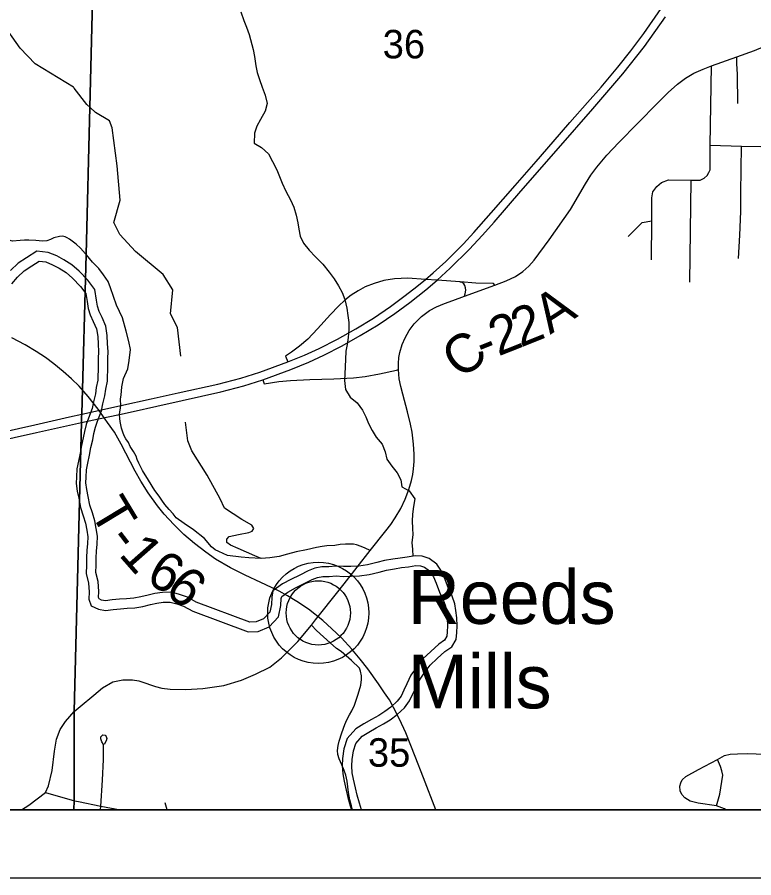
# Model space of a CAD drawing. Extents: x 0 to 34, y 0 to 22.
# Drawn here: x 4.467 to 5.55, y 14 to 15.265 of the extents above; entities that cross this region are included whole.
import ezdxf

# ---------------------------------------------------------------- set-up
doc = ezdxf.new("R2010")
doc.units = 0
for name, color, linetype in [('GM_X_Corporation', 7, 'Continuous'), ('GM_X_County_Road', 7, 'Continuous'), ('GM_X_County_Road_Text', 7, 'Continuous'), ('GM_X_Interchange_Ramps', 7, 'Continuous'), ('GM_X_Minor_River', 7, 'Continuous'), ('GM_X_Rail_Line', 7, 'Continuous'), ('GM_X_Section_Text', 7, 'Continuous'), ('GM_X_Township_Road', 7, 'Continuous'), ('GM_X_Township_Road_Text', 7, 'Continuous'), ('GM_X_Unincorporated', 7, 'Continuous'), ('GM_X_Unincorporated_Location', 7, 'Continuous'), ('GM_X_Unincorporated_Text', 7, 'Continuous'), ('GM_X_US_Route', 7, 'Continuous'), ('SH_Data', 7, 'Continuous')]:
    doc.layers.add(name, color=color, linetype=linetype)

msp = doc.modelspace()

# ---------------------------------------------------------------- linework, layer by layer
at = {"layer": 'GM_X_Corporation'}
msp.add_lwpolyline([(5.6014, 15.7658), (5.4664, 15.7674), (4.5888, 15.778), (4.5873, 15.6794), (4.5738, 15.1325), (4.5685, 14.9157), (4.5617, 14.6817), (4.5616, 14.6767), (4.5614, 14.6695), (4.5505, 14.2449), (4.5507, 14.1138), (4.5503, 14.1), (8.9, 14.1)], dxfattribs=at)
msp.add_lwpolyline([(2.1, 15.7148), (2.1, 14.1), (4.5503, 14.1), (4.5507, 14.1138), (4.5505, 14.2449), (4.5614, 14.6695), (4.5616, 14.6767), (4.5617, 14.6817), (4.5685, 14.9157), (4.5738, 15.1325), (4.5873, 15.6794), (4.2138, 15.6834), (3.9277, 15.6898), (3.3171, 15.6975), (2.4078, 15.7088)], close=True, dxfattribs=at)
at = {"layer": 'GM_X_County_Road'}
msp.add_line((4.8997, 14.3711), (4.9056, 14.3789), dxfattribs=at)
for points in [[(5.4875, 15.1929), (5.5249, 15.2062), (5.5509, 15.2158), (5.5765, 15.2264)], [(5.169, 14.8707), (5.1858, 14.877), (5.1997, 14.8836), (5.2102, 14.8908), (5.2192, 14.8985), (5.227, 14.9074), (5.2489, 14.9374), (5.2804, 14.9818), (5.3025, 15.0199), (5.3105, 15.0326), (5.319, 15.0444), (5.334, 15.0616), (5.3517, 15.0802), (5.3796, 15.1089), (5.4083, 15.1384), (5.4241, 15.1541), (5.4375, 15.1661), (5.4496, 15.1749), (5.4617, 15.1821), (5.4756, 15.1882), (5.4875, 15.1929)], [(5.0276, 14.7468), (5.0274, 14.7555), (5.0282, 14.7645), (5.0295, 14.7719), (5.0327, 14.7834), (5.0371, 14.7935), (5.0432, 14.8043), (5.0507, 14.8141), (5.0614, 14.8248), (5.0733, 14.8336), (5.0834, 14.8389), (5.0954, 14.844), (5.1074, 14.8483), (5.1245, 14.8546), (5.169, 14.8707)], [(4.9861, 14.4808), (5.0089, 14.5096), (5.0161, 14.5193), (5.0227, 14.5289), (5.0311, 14.5427), (5.0375, 14.5563), (5.0428, 14.5706), (5.0467, 14.5839), (5.0486, 14.5925), (5.0498, 14.601), (5.0505, 14.6115), (5.0505, 14.6225), (5.0497, 14.6373), (5.0475, 14.655), (5.0453, 14.6665), (5.0406, 14.6849), (5.0338, 14.7107), (5.0309, 14.7219), (5.0287, 14.733), (5.0276, 14.7468)], [(4.9056, 14.3789), (4.9151, 14.3914), (4.9474, 14.432), (4.9861, 14.4808)], [(4.6488, 14.2883), (4.6703, 14.2813), (4.6796, 14.2784), (4.6916, 14.2772), (4.7148, 14.2769), (4.74, 14.2781), (4.7706, 14.2825), (4.7966, 14.2904), (4.8175, 14.2992), (4.8381, 14.3093), (4.8557, 14.3232), (4.8795, 14.347), (4.8997, 14.3711)], [(4.473, 14.1), (4.484, 14.1067), (4.5085, 14.1253), (4.5127, 14.1352), (4.5181, 14.1578), (4.5216, 14.1861), (4.5247, 14.2038), (4.5303, 14.2179), (4.5377, 14.2295), (4.5507, 14.2443), (4.5595, 14.2518), (4.5796, 14.2683), (4.5925, 14.2793), (4.6074, 14.2878), (4.622, 14.2909), (4.6365, 14.2911), (4.6458, 14.2892), (4.6488, 14.2883)]]:
    msp.add_lwpolyline(points, dxfattribs=at)
at = {"layer": 'GM_X_Interchange_Ramps'}
for points in [[(5.169, 14.8707), (5.1671, 14.873), (5.1412, 14.8737), (5.1181, 14.8759), (5.0845, 14.8781), (5.0671, 14.8793), (5.0412, 14.881), (5.0214, 14.8801), (5.0059, 14.8775), (4.9916, 14.8734), (4.9785, 14.8681), (4.9681, 14.8627), (4.9579, 14.856), (4.9485, 14.8487), (4.9392, 14.8401), (4.9275, 14.8278), (4.9082, 14.8067), (4.894, 14.7915), (4.8822, 14.7812), (4.8701, 14.7722), (4.8615, 14.7666), (4.8649, 14.7579)], [(5.1245, 14.8546), (5.1255, 14.8579), (5.1265, 14.8633), (5.1262, 14.867), (5.125, 14.8705), (5.1234, 14.8728), (5.1213, 14.8745), (5.118, 14.8751), (5.1181, 14.8759)], [(4.8279, 14.7316), (4.83, 14.7259), (4.8514, 14.7291), (4.8686, 14.7309), (4.8972, 14.7323), (4.9324, 14.7331), (4.9616, 14.7344), (4.9787, 14.7365), (4.9996, 14.7405), (5.0245, 14.7457), (5.0276, 14.7468)]]:
    msp.add_lwpolyline(points, dxfattribs=at)
at = {"layer": 'GM_X_Minor_River'}
for points in [[(4.7958, 15.2723), (4.8002, 15.2598), (4.8042, 15.25), (4.8082, 15.2391), (4.814, 15.2172), (4.8158, 15.2066), (4.8179, 15.1929), (4.8197, 15.1831), (4.8233, 15.1732), (4.8273, 15.1619), (4.8313, 15.1502), (4.8346, 15.1377), (4.8314, 15.1263), (4.8245, 15.1143), (4.8194, 15.1044), (4.8158, 15.094), (4.8153, 15.0796), (4.8261, 15.0729), (4.8365, 15.0636), (4.8421, 15.0523), (4.8488, 15.0403), (4.8524, 15.0305), (4.8564, 15.0207), (4.862, 15.009), (4.8687, 14.9962), (4.8735, 14.9853), (4.8771, 14.9736), (4.8796, 14.9626), (4.881, 14.9531), (4.8831, 14.9429), (4.8878, 14.9327), (4.8964, 14.9223), (4.9054, 14.9122), (4.9162, 14.9017), (4.9256, 14.8898), (4.933, 14.88), (4.9393, 14.8699), (4.9448, 14.8601), (4.9484, 14.8495), (4.9517, 14.8371), (4.9531, 14.8261), (4.9544, 14.8158), (4.9546, 14.8056), (4.9537, 14.7941), (4.9521, 14.7835), (4.95, 14.7739), (4.9495, 14.7617), (4.9489, 14.7511), (4.9488, 14.74), (4.9482, 14.7305), (4.9496, 14.7173), (4.9563, 14.706), (4.9667, 14.6978), (4.9745, 14.6873), (4.9793, 14.6775), (4.9833, 14.6677), (4.9888, 14.6572), (4.9947, 14.6474), (5.0033, 14.6373), (5.0077, 14.626), (5.0106, 14.6151), (5.0176, 14.6049), (5.0258, 14.5952), (5.031, 14.5847), (5.0323, 14.5744), (5.0431, 14.5686), (5.0513, 14.5566), (5.0496, 14.5455), (5.0483, 14.5345), (5.0474, 14.5238), (5.048, 14.5139), (5.0486, 14.5037), (5.0469, 14.4926), (5.0479, 14.4824), (5.0488, 14.4724)], [(4.7302, 14.405), (4.7172, 14.4123), (4.7056, 14.4162), (4.6938, 14.4195), (4.6804, 14.4193), (4.6695, 14.4175), (4.6595, 14.4154), (4.6488, 14.4127), (4.6382, 14.4109), (4.6274, 14.4101), (4.6175, 14.4093), (4.6065, 14.4084), (4.5969, 14.4071), (4.5908, 14.4081), (4.5872, 14.4099), (4.5865, 14.4119), (4.5867, 14.4205), (4.5857, 14.4352), (4.5827, 14.4486), (4.583, 14.4592), (4.5829, 14.4703), (4.5835, 14.4798), (4.5846, 14.4903), (4.5849, 14.5021), (4.5831, 14.5131), (4.5809, 14.5246), (4.5775, 14.5361), (4.5738, 14.5476), (4.5712, 14.5604), (4.5693, 14.5706), (4.5679, 14.5801), (4.5682, 14.5886), (4.5687, 14.5992), (4.5707, 14.6091), (4.5733, 14.621), (4.5754, 14.6323), (4.578, 14.6433), (4.5798, 14.6527), (4.5821, 14.662), (4.5852, 14.6708), (4.5908, 14.6859), (4.5927, 14.6965), (4.5957, 14.7082), (4.5972, 14.718), (4.5996, 14.7295), (4.6002, 14.7523), (4.6001, 14.763), (4.6004, 14.7735), (4.5999, 14.7846), (4.5994, 14.797), (4.597, 14.8105), (4.5916, 14.8232), (4.5873, 14.8323), (4.5851, 14.8398), (4.5836, 14.8489), (4.5811, 14.8645), (4.5708, 14.8781), (4.5582, 14.8913), (4.5473, 14.9007), (4.5357, 14.9079), (4.5252, 14.9137), (4.5126, 14.9189), (4.4958, 14.9207), (4.4806, 14.9111), (4.4681, 14.903), (4.4568, 14.8924)], [(4.4588, 14.8727), (4.4671, 14.8826), (4.4769, 14.8918), (4.4882, 14.8991), (4.4992, 14.906), (4.5091, 14.905), (4.519, 14.9009), (4.5285, 14.8956), (4.5389, 14.8893), (4.5484, 14.881), (4.5599, 14.8689), (4.5676, 14.8587), (4.5696, 14.8466), (4.5712, 14.8367), (4.574, 14.8272), (4.5786, 14.8174), (4.5833, 14.8064), (4.5853, 14.7954), (4.5857, 14.784), (4.5862, 14.7734), (4.5859, 14.7631), (4.586, 14.7525), (4.5854, 14.7312), (4.5832, 14.7205), (4.5818, 14.711), (4.5789, 14.6996), (4.577, 14.6897), (4.5718, 14.6756), (4.5685, 14.6661), (4.5659, 14.6558), (4.5641, 14.6463), (4.5615, 14.6352), (4.5594, 14.6238), (4.5568, 14.612), (4.5546, 14.601), (4.554, 14.5892), (4.5537, 14.5793), (4.5553, 14.5683), (4.5573, 14.5577), (4.56, 14.544), (4.5639, 14.5319), (4.5671, 14.5213), (4.5691, 14.5106), (4.5707, 14.5012), (4.5704, 14.4913), (4.5693, 14.481), (4.5686, 14.4707), (4.5687, 14.4593), (4.5685, 14.4472), (4.5716, 14.4331), (4.5725, 14.4202), (4.5722, 14.4096), (4.5757, 14.3997), (4.5864, 14.3945), (4.5967, 14.3927), (4.6081, 14.3943), (4.6187, 14.3951), (4.6286, 14.396), (4.6399, 14.3968), (4.6517, 14.3988), (4.6627, 14.4016), (4.6722, 14.4036), (4.6817, 14.4052), (4.6919, 14.4052), (4.7014, 14.4027), (4.7113, 14.3993), (4.725, 14.3918)], [(4.9731, 14.1), (4.97, 14.1098), (4.9667, 14.1215), (4.9642, 14.1321), (4.9613, 14.1449), (4.9596, 14.1544), (4.959, 14.1643), (4.9596, 14.1738), (4.9612, 14.1864), (4.9648, 14.1975), (4.9741, 14.2079), (4.9838, 14.2142), (4.9947, 14.2201), (5.0056, 14.2264), (5.0154, 14.2323), (5.0255, 14.2397), (5.0363, 14.2498), (5.0437, 14.2599), (5.048, 14.2695), (5.0528, 14.2791), (5.0583, 14.2906), (5.0653, 14.3006), (5.0741, 14.3122), (5.0846, 14.3223), (5.0958, 14.3324), (5.1059, 14.3394), (5.1121, 14.3502), (5.1134, 14.3605), (5.1136, 14.3704), (5.1134, 14.3818), (5.112, 14.3928), (5.1103, 14.4026), (5.1063, 14.4139), (5.1011, 14.4252), (5.0963, 14.4381), (5.0915, 14.449), (5.0837, 14.4606), (5.0728, 14.4692), (5.0625, 14.4728), (5.0522, 14.4729), (5.0401, 14.4712), (5.0299, 14.4698), (5.0193, 14.4681), (5.0068, 14.466), (4.9955, 14.4631), (4.9818, 14.4598), (4.969, 14.458), (4.9576, 14.4574), (4.9466, 14.4572), (4.9355, 14.4577), (4.9249, 14.4567), (4.915, 14.4569), (4.9044, 14.4548), (4.8946, 14.4512), (4.8826, 14.4449), (4.8694, 14.4385), (4.857, 14.4318), (4.8428, 14.4216), (4.8411, 14.4121), (4.8406, 14.4018), (4.8381, 14.3904), (4.8292, 14.3807), (4.8183, 14.3759), (4.8088, 14.3757), (4.7302, 14.405)], [(4.725, 14.3918), (4.8064, 14.3615), (4.8214, 14.3618), (4.8376, 14.3689), (4.8512, 14.3836), (4.8547, 14.4), (4.8552, 14.4105), (4.8558, 14.4134), (4.8646, 14.4197), (4.8759, 14.4259), (4.889, 14.4322), (4.9004, 14.4382), (4.9083, 14.4411), (4.9163, 14.4427), (4.9254, 14.4425), (4.9358, 14.4435), (4.9464, 14.4429), (4.9581, 14.4432), (4.9703, 14.4438), (4.9845, 14.4458), (4.9989, 14.4493), (5.0098, 14.4521), (5.0216, 14.4541), (5.032, 14.4558), (5.0421, 14.4571), (5.0532, 14.4587), (5.06, 14.4586), (5.0659, 14.4565), (5.0731, 14.4509), (5.079, 14.4421), (5.0831, 14.4327), (5.088, 14.4198), (5.0931, 14.4086), (5.0965, 14.399), (5.098, 14.3907), (5.0992, 14.3808), (5.0994, 14.3704), (5.0992, 14.3615), (5.0984, 14.3548), (5.0952, 14.3493), (5.0869, 14.3435), (5.0749, 14.3326), (5.0635, 14.3217), (5.0538, 14.309), (5.0459, 14.2977), (5.04, 14.2852), (5.0352, 14.2755), (5.0314, 14.2671), (5.0256, 14.2593), (5.0164, 14.2507), (5.0075, 14.2441), (4.9984, 14.2386), (4.9878, 14.2325), (4.9766, 14.2264), (4.9648, 14.2188), (4.9522, 14.2047), (4.9473, 14.1895), (4.9454, 14.1751), (4.9448, 14.1643), (4.9455, 14.1527), (4.9474, 14.1421), (4.9504, 14.1289), (4.953, 14.1179), (4.9564, 14.1057), (4.9582, 14.1)]]:
    msp.add_lwpolyline(points, dxfattribs=at)
at = {"layer": 'GM_X_Rail_Line'}
msp.add_lwpolyline([(5.0824, 14.1), (5.0641, 14.1469), (5.0522, 14.1781), (5.0382, 14.213), (5.0291, 14.2329), (5.0201, 14.2504), (5.0141, 14.2614), (5.0071, 14.2719), (4.9983, 14.2852), (4.9826, 14.3071), (4.9713, 14.3212), (4.9591, 14.336), (4.9437, 14.3524), (4.9295, 14.3659), (4.9161, 14.3779), (4.895, 14.3946), (4.8782, 14.4061), (4.8645, 14.4142), (4.8522, 14.4212), (4.8408, 14.4266), (4.8252, 14.434), (4.802, 14.4449), (4.7804, 14.4553), (4.7587, 14.4682), (4.7442, 14.4783), (4.7275, 14.4912), (4.7117, 14.5046), (4.697, 14.5191), (4.6831, 14.5343), (4.6731, 14.5466), (4.6594, 14.5658), (4.6486, 14.5828), (4.6403, 14.5973), (4.6198, 14.6372), (4.6098, 14.6548), (4.5999, 14.669), (4.5857, 14.6888), (4.5714, 14.7074), (4.5578, 14.7223), (4.5465, 14.7334), (4.5344, 14.7441), (4.5208, 14.7551), (4.5085, 14.7645), (4.4948, 14.7734), (4.4787, 14.7833), (4.4588, 14.7935)], dxfattribs=at)
at = {"layer": 'GM_X_Township_Road'}
for p, q in [((5.456, 14.8751), (5.4577, 15.0251)), ((5.3997, 14.9078), (5.3999, 14.9653)), ((4.8997, 14.3711), (4.9056, 14.3789)), ((4.6875, 14.1), (4.6845, 14.1102))]:
    msp.add_line(p, q, dxfattribs=at)
for points in [[(4.5502, 15.1611), (4.5496, 15.1619), (4.4934, 15.1962), (4.4711, 15.219), (4.4444, 15.2572), (4.4269, 15.3047), (4.385, 15.3914), (4.3689, 15.4195), (4.3582, 15.4397), (4.3417, 15.4652), (4.3172, 15.495), (4.2948, 15.5298), (4.2586, 15.6149), (4.235, 15.6314), (4.2175, 15.6447), (4.2125, 15.6544), (4.2131, 15.6659), (4.214, 15.6829), (4.2126, 15.6897)], [(5.5263, 15.1378), (5.526, 15.1805), (5.5249, 15.1967), (5.5249, 15.2062)], [(5.3654, 14.9425), (5.386, 14.9628), (5.3999, 14.9653), (5.3999, 14.9992), (5.4017, 15.0078), (5.4073, 15.0159), (5.4141, 15.0218), (5.4246, 15.0258), (5.4577, 15.0251), (5.4713, 15.0251), (5.4768, 15.0278), (5.4812, 15.0317), (5.484, 15.0363), (5.4856, 15.0403), (5.4856, 15.0765), (5.4875, 15.1929)], [(4.7073, 14.7664), (4.7028, 14.8088), (4.6923, 14.8287), (4.6959, 14.8641), (4.6815, 14.8866), (4.6409, 14.9204), (4.6178, 14.945), (4.6092, 14.9631), (4.6185, 14.9955), (4.6139, 15.0462), (4.6065, 15.1018), (4.6026, 15.1124), (4.5819, 15.1245), (4.574, 15.132), (4.5693, 15.1365), (4.5508, 15.1604), (4.5502, 15.1611)], [(5.4856, 15.0765), (5.5316, 15.0751), (5.6175, 15.0734), (5.7756, 15.07), (5.8199, 15.0688)], [(5.5275, 14.9102), (5.5292, 14.9441), (5.5307, 14.9789), (5.5311, 15.0063), (5.5316, 15.0751)], [(4.5674, 14.9167), (4.5601, 14.9253), (4.5535, 14.9308), (4.544, 14.9384), (4.5404, 14.9404), (4.5373, 14.9417), (4.5334, 14.9426), (4.5291, 14.9422), (4.5209, 14.9401), (4.5158, 14.9378), (4.5107, 14.936), (4.5041, 14.9356), (4.4942, 14.9365), (4.4841, 14.9371), (4.4778, 14.9367), (4.4713, 14.9363), (4.46, 14.9352), (4.447, 14.9391)], [(4.6186, 14.7037), (4.6197, 14.7094), (4.6209, 14.7213), (4.6231, 14.7335), (4.6296, 14.7479), (4.6316, 14.76), (4.6334, 14.7762), (4.6308, 14.7879), (4.6272, 14.803), (4.6219, 14.8228), (4.613, 14.8415), (4.6042, 14.867), (4.6004, 14.8762), (4.594, 14.8861), (4.587, 14.8952), (4.5775, 14.9048), (4.5687, 14.9152), (4.5674, 14.9167)], [(4.8258, 14.4691), (4.8077, 14.4702), (4.7961, 14.4713), (4.7763, 14.4736), (4.7632, 14.4794), (4.7578, 14.4818), (4.7524, 14.4864), (4.7425, 14.4984), (4.726, 14.5114), (4.7122, 14.5205), (4.7006, 14.529), (4.696, 14.5348), (4.6901, 14.5414), (4.684, 14.5487), (4.6795, 14.555), (4.6754, 14.5607), (4.6694, 14.5691), (4.66, 14.5841), (4.6512, 14.5986), (4.6459, 14.6093), (4.6435, 14.6146), (4.6417, 14.6195), (4.6378, 14.6265), (4.633, 14.6338), (4.6307, 14.6395), (4.6268, 14.6452), (4.6241, 14.6493), (4.622, 14.6549), (4.6204, 14.6606), (4.6193, 14.6656), (4.6182, 14.6703), (4.6176, 14.6751), (4.6172, 14.6809), (4.6192, 14.694), (4.6186, 14.7028), (4.6186, 14.7037)], [(4.8258, 14.4691), (4.8161, 14.4732), (4.7919, 14.4837), (4.7804, 14.4886), (4.7749, 14.4928), (4.7749, 14.4976), (4.7785, 14.5015), (4.7923, 14.5044), (4.8077, 14.5072), (4.8122, 14.5095), (4.8147, 14.5133), (4.8119, 14.5183), (4.797, 14.5263), (4.7718, 14.543), (4.7655, 14.5566), (4.746, 14.5914), (4.7238, 14.6275), (4.7178, 14.6419), (4.7145, 14.6697)], [(4.9861, 14.4808), (4.9786, 14.4843), (4.9726, 14.4867), (4.9658, 14.4891), (4.9612, 14.49), (4.9563, 14.4902), (4.9497, 14.4902), (4.9418, 14.4898), (4.9339, 14.4884), (4.9223, 14.4876), (4.9152, 14.4869), (4.9071, 14.4851), (4.8921, 14.4821), (4.8772, 14.4788), (4.8642, 14.4754), (4.8521, 14.4721), (4.8381, 14.4699), (4.8258, 14.4691)], [(4.9056, 14.3789), (4.9151, 14.3914), (4.9474, 14.432), (4.9861, 14.4808)], [(4.9601, 14.1), (4.9583, 14.1057), (4.9559, 14.1147), (4.9542, 14.1252), (4.953, 14.1336), (4.9519, 14.1422), (4.9502, 14.1507), (4.9475, 14.1578), (4.9443, 14.1659), (4.9403, 14.1749), (4.9383, 14.1811), (4.9379, 14.187), (4.9388, 14.1945), (4.9401, 14.2009), (4.944, 14.2132), (4.9487, 14.225), (4.9517, 14.2323), (4.9555, 14.2393), (4.9588, 14.2455), (4.9626, 14.2537), (4.9676, 14.2685), (4.9695, 14.2749), (4.9719, 14.2829), (4.9731, 14.2916), (4.973, 14.2969), (4.9717, 14.3038), (4.97, 14.3081), (4.9585, 14.3193), (4.9431, 14.3323), (4.9366, 14.337), (4.9269, 14.3451), (4.9172, 14.3543), (4.9071, 14.3635), (4.8997, 14.3711)], [(4.5896, 14.1), (4.5898, 14.1053), (4.5923, 14.1436), (4.5936, 14.174), (4.5938, 14.1958), (4.5913, 14.1996), (4.5899, 14.2041), (4.59, 14.2073), (4.5927, 14.21), (4.5961, 14.2097), (4.5978, 14.2078), (4.5985, 14.2047), (4.5979, 14.2011), (4.5949, 14.1959)], [(5.5088, 14.1), (5.5067, 14.1012), (5.495, 14.1059), (5.4683, 14.1095), (5.4565, 14.1127), (5.4483, 14.1177), (5.4441, 14.1224), (5.4417, 14.1278), (5.4411, 14.1344), (5.4425, 14.1395), (5.4448, 14.1438), (5.4501, 14.149), (5.4684, 14.1591), (5.4966, 14.1736), (5.5066, 14.1797), (5.5151, 14.1818), (5.5262, 14.1822), (5.5406, 14.1825), (5.5793, 14.1812)], [(5.495, 14.1059), (5.5002, 14.123), (5.5045, 14.1507), (5.5028, 14.157), (5.5008, 14.1633), (5.4966, 14.1736)], [(4.5085, 14.1253), (4.5509, 14.1132), (4.5569, 14.112)], [(4.5569, 14.112), (4.5898, 14.1053), (4.6188, 14.1)]]:
    msp.add_lwpolyline(points, dxfattribs=at)
at = {"layer": 'GM_X_Unincorporated'}
for radius in [0.0744, 0.0472]:
    msp.add_circle((4.9096, 14.3892), radius, dxfattribs=at)
at = {"layer": 'GM_X_Unincorporated_Location'}
msp.add_line((4.9096, 14.3892), (4.9096, 14.3892), dxfattribs=at)
at = {"layer": 'GM_X_US_Route'}
for points in [[(4.8649, 14.7579), (4.8891, 14.7678), (4.9109, 14.7778), (4.9378, 14.7916), (4.9646, 14.8066), (4.9906, 14.8225), (5.0156, 14.8394), (5.0374, 14.8555), (5.0544, 14.8687), (5.0671, 14.8793), (5.0783, 14.8888), (5.097, 14.9057), (5.1231, 14.9316), (5.1385, 14.9481), (5.1638, 14.9769), (5.1989, 15.0173), (5.2299, 15.0526), (5.2549, 15.0813), (5.2796, 15.1097), (5.3053, 15.139), (5.3253, 15.1619), (5.3501, 15.1911), (5.3692, 15.2152), (5.388, 15.2404), (5.4139, 15.2775)], [(4.8279, 14.7316), (4.8693, 14.7467), (4.8958, 14.7578), (4.9177, 14.7677), (4.9446, 14.7815), (4.9714, 14.7966), (4.9974, 14.8124), (5.0223, 14.8294), (5.0442, 14.8454), (5.0677, 14.8641), (5.0845, 14.8781), (5.1037, 14.8956), (5.1314, 14.923), (5.1509, 14.9441), (5.1681, 14.9636), (5.2074, 15.0088), (5.2628, 15.0722), (5.3131, 15.1298), (5.3573, 15.1811), (5.389, 15.2214), (5.4201, 15.265)], [(4.4248, 14.6506), (4.4927, 14.6658), (4.5437, 14.6771), (4.5619, 14.6812), (4.5819, 14.6856), (4.6192, 14.694), (4.6641, 14.7037), (4.7037, 14.7124), (4.7621, 14.7253), (4.7956, 14.7341), (4.8235, 14.7428), (4.8649, 14.7579)], [(4.6372, 14.6853), (4.6723, 14.6931), (4.7096, 14.7013), (4.7665, 14.7141), (4.8, 14.723), (4.8279, 14.7316)], [(4.4292, 14.6394), (4.4955, 14.6541), (4.5481, 14.6659), (4.5616, 14.6689), (4.5863, 14.6744), (4.6172, 14.6809), (4.6372, 14.6853)]]:
    msp.add_lwpolyline(points, dxfattribs=at)
at = {"layer": 'SH_Data'}
msp.add_line((2, 14), (9, 14), dxfattribs=at)
msp.add_lwpolyline([(2.1, 20.9), (8.9, 20.9), (8.9, 14.1), (2.1, 14.1)], close=True, dxfattribs=at)

# ---------------------------------------------------------------- texts
at = {"layer": 'GM_X_County_Road_Text'}
for s, rotation, p in [('A', 33.3862, (5.2505, 14.7977)), ('2', 21.8428, (5.207, 14.7789)), ('2', 21.6043, (5.1742, 14.7659)), ('C', 36.8699, (5.1187, 14.7312)), ('-', 21.8014, (5.1526, 14.7573))]:
    msp.add_text(s, height=0.0568, rotation=rotation, dxfattribs=at).set_placement(p)
at = {"layer": 'GM_X_Section_Text'}
for s, p in [('36', (5.0043, 15.204)), ('35', (4.9826, 14.1632))]:
    msp.add_text(s, height=0.04186, rotation=0, dxfattribs=at).set_placement(p)
at = {"layer": 'GM_X_Township_Road_Text'}
for s, rotation, p in [('T', 301.1074, (4.5725, 14.538)), ('-', 307.4318, (4.5983, 14.496)), ('1', 311.325, (4.615, 14.4744)), ('6', 330.4356, (4.6539, 14.4353)), ('6', 319.7008, (4.6818, 14.4198))]:
    msp.add_text(s, height=0.0568, rotation=rotation, dxfattribs=at).set_placement(p)
at = {"layer": 'GM_X_Unincorporated_Text'}
for s, p in [('Reeds', (5.0414, 14.3731)), ('Mills', (5.0414, 14.2489))]:
    msp.add_text(s, height=0.07898, rotation=0, dxfattribs=at).set_placement(p)

doc.saveas('drawing.dxf')
